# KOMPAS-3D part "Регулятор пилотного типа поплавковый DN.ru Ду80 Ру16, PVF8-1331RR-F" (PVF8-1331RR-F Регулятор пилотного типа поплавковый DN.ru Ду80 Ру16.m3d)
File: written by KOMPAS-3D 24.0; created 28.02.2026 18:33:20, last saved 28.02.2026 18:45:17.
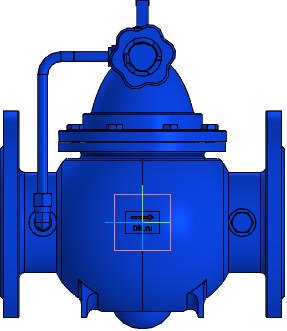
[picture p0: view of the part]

Document properties: Автор: R2D2; Полное имя файла: E:\Работа\Зайцев\PVF8-1331RR-F Регулятор пилотного типа поплавковый DN.ru Ду15-300\DN80\PVF8-1331RR-F Регулятор пилотного типа поплавковый DN.ru Ду80 Ру16.m3d

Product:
- Part/product: Регулятор пилотного типа поплавковый DN.ru Ду80 Ру16  | designation PVF8-1331RR-F
    Масса: 13
    Раздел спецификации: Прочие изделия
    Примечание: D230-10613
    additional columns: D230-10613

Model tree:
1. Операция без истории:2

Expressions: PVF8-1331RR-F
